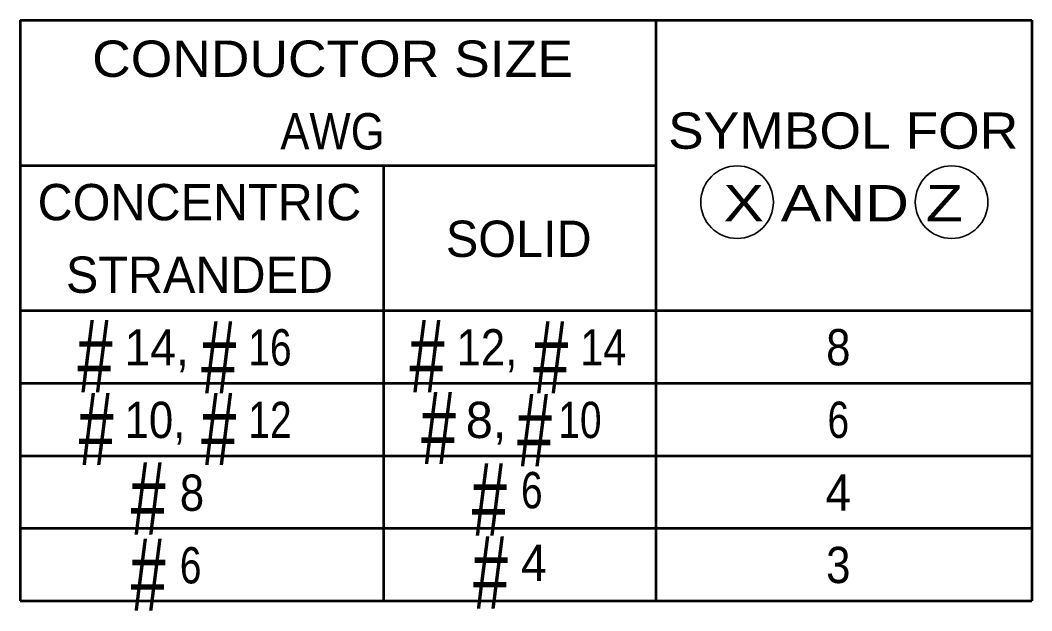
# Model space of a CAD drawing. Extents: x -1 to 679, y 0 to 440.
# Drawn here: x 344 to 399.7, y 76.1 to 108.7 of the extents above; entities that cross this region are included whole.
import ezdxf
from ezdxf.enums import TextEntityAlignment as Align

# ---------------------------------------------------------------- set-up
doc = ezdxf.new("R2010")
doc.units = 0
doc.header["$LTSCALE"] = 0.8
doc.layers.add('1', color=7, linetype='Continuous', lineweight=53)

msp = doc.modelspace()

# ---------------------------------------------------------------- linework, layer by layer
at = {"layer": '1'}
for p, q in [((343.9642, 108.6769), (343.9642, 76.6769)), ((378.9642, 108.6769), (378.9642, 76.6769)), ((399.6761, 108.6769), (399.6761, 76.6769)), ((343.9642, 100.6769), (378.9642, 100.6769)), ((363.9642, 100.6769), (363.9642, 76.6769)), ((343.9642, 92.6769), (399.6761, 92.6769)), ((343.9642, 88.6769), (399.6761, 88.6769)), ((343.9642, 84.6769), (399.6761, 84.6769)), ((343.9642, 80.6769), (399.6761, 80.6769)), ((343.9642, 76.6769), (399.6761, 76.6769))]:
    msp.add_line(p, q, dxfattribs=at)
msp.add_lwpolyline([(343.9642, 108.6769), (378.9642, 108.6769), (399.6761, 108.6769)], dxfattribs=at)
at = {"layer": '1', "lineweight": 35}
for centre in [(383.4462, 98.6487), (395.2618, 98.6487)]:
    msp.add_circle(centre, 2, dxfattribs=at)

# ---------------------------------------------------------------- texts
at = {"layer": '1'}
for s, width, p in [('CONDUCTOR SIZE', 1.1, (361.1635, 105.5562)), ('AWG', 0.9, (361.1634, 101.5562)), ('SYMBOL FOR', 1.1, (389.2901, 101.5938)), ('X AND Z', 1.25, (389.2901, 97.5938)), ('8', 0.9, (389.021, 89.6569)), ('6', 0.8, (389.021, 85.6569)), ('4', 0.95, (389.021, 81.6569)), ('3', 0.9, (389.021, 77.6569))]:
    msp.add_text(s, height=2, dxfattribs=dict(at, width=width)).set_placement(p, align=Align.CENTER)
for s, p in [('CONCENTRIC', (353.8356, 97.6522)), ('STRANDED', (353.8355, 93.6522))]:
    msp.add_text(s, height=2, dxfattribs=at).set_placement(p, align=Align.CENTER)
for s, p in [('SOLID', (367.408, 95.6324)), ('8,', (368.5051, 85.6498))]:
    msp.add_text(s, height=2, dxfattribs=at).set_placement(p)
for s, height, width, p in [('#', 4, 0.65, (347.1156, 88.1701)), ('#', 4, 0.65, (353.9315, 88.1063)), ('#', 4, 0.65, (365.3976, 88.1701)), ('#', 4, 0.65, (372.2135, 88.1063)), ('14,', 2, 0.95, (349.7134, 89.6498)), ('16', 2, 0.8, (356.5293, 89.6498)), ('12,', 2, 0.9, (367.9954, 89.6498)), ('14', 2, 0.85, (374.8113, 89.6498)), ('#', 4, 0.65, (347.1793, 84.1557)), ('#', 4, 0.65, (353.9315, 84.1556)), ('#', 4, 0.65, (366.0346, 84.2194)), ('#', 4, 0.65, (371.3217, 84.0919)), ('10,', 2, 0.9, (349.7134, 85.6498)), ('12', 2, 0.8, (356.5293, 85.6498)), ('10', 2, 0.8, (373.601, 85.6497)), ('#', 4, 0.65, (350.0457, 80.3323)), ('#', 4, 0.65, (368.8373, 80.2724)), ('8', 2, 0.9, (352.7537, 81.6382)), ('6', 2, 0.8, (371.5453, 81.78)), ('#', 4, 0.65, (368.8991, 76.256)), ('#', 4, 0.65, (350.0457, 76.1306)), ('4', 2, 0.95, (371.5453, 77.78)), ('6', 2, 0.8, (352.7537, 77.6382))]:
    msp.add_text(s, height=height, dxfattribs=dict(at, width=width)).set_placement(p)

doc.saveas('drawing.dxf')
